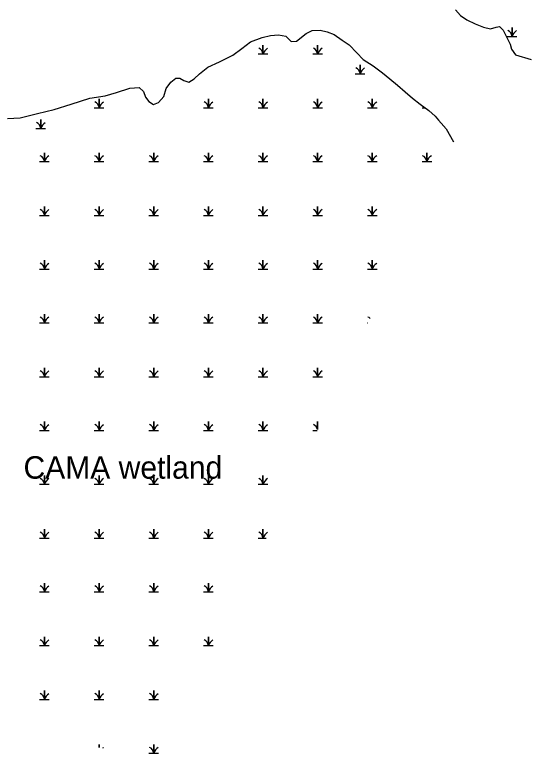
# Model space of a CAD drawing. Extents: x 2678633 to 2679425, y 623836 to 624637.
# Drawn here: x 2679137.9 to 2679367.7, y 623835.7 to 624164.5 of the extents above; entities that cross this region are included whole.
import ezdxf

# ---------------------------------------------------------------- set-up
doc = ezdxf.new("R2010")
doc.units = 0
for name, color, linetype in [('Exist Environmental Wetland Boundary Text', 7, 'Continuous'), ('Exist Hydro Jurisdictional Stream or Body of Water NEU Mitigable', 7, 'Continuous'), ('Exist Hydro Swamp or Marsh', 7, 'Continuous')]:
    doc.layers.add(name, color=color, linetype=linetype)

msp = doc.modelspace()

# ---------------------------------------------------------------- linework, layer by layer
at = {"layer": 'Exist Hydro Jurisdictional Stream or Body of Water NEU Mitigable'}
for points in [[(2679334.08, 624166.66), (2679336.33, 624164.17), (2679339.07, 624162.2), (2679342.8, 624160.42), (2679346.48, 624158.91), (2679349.63, 624158.24), (2679352.09, 624158.97), (2679353.62, 624159.26), (2679355.24, 624157.61), (2679358.4, 624151.43), (2679358.97, 624149.18), (2679360.71, 624146.65), (2679367.73, 624144.62)], [(2679134.61, 624118.28), (2679140.32, 624118.54), (2679148.07, 624120.5), (2679155.36, 624122.34), (2679162.99, 624124.69), (2679171.25, 624127.4), (2679178.18, 624128.34), (2679183.22, 624129.83), (2679189.12, 624131.8), (2679193.26, 624132.05), (2679195.22, 624130.3), (2679196.06, 624127.78), (2679197.62, 624125.82), (2679199.59, 624124.48), (2679201.9, 624125.43), (2679204.16, 624128.12), (2679205.25, 624131.69), (2679207.39, 624134.48), (2679209.56, 624136.27), (2679211.29, 624136.22), (2679213.18, 624135.22), (2679215.4, 624134.49), (2679217.68, 624135.97), (2679220.11, 624138.13), (2679223.75, 624141.11), (2679229.04, 624143.47), (2679234.87, 624146.52), (2679238.99, 624149.51), (2679242.78, 624152.42), (2679248.03, 624154.34), (2679251.69, 624155.25), (2679255.22, 624155.61), (2679258.48, 624154.9), (2679260.89, 624152.59), (2679263.21, 624152.67), (2679267.57, 624156.14), (2679270.19, 624157.44), (2679273.82, 624157.6), (2679276.99, 624156.87), (2679280.02, 624155.71), (2679283.63, 624153.2), (2679286.68, 624151.13), (2679290.11, 624147.47), (2679292.95, 624144.59), (2679297.35, 624141.67), (2679301.58, 624138.59), (2679304.86, 624135.98), (2679308.27, 624133.13), (2679311.62, 624130.12), (2679314.85, 624127.33), (2679318.38, 624124.68), (2679322.22, 624121.85), (2679324.99, 624119.26), (2679326.47, 624117.59), (2679327.71, 624116.19), (2679329.95, 624113.66), (2679333.14, 624107.89)]]:
    msp.add_lwpolyline(points, dxfattribs=at)
at = {"layer": 'Exist Hydro Swamp or Marsh'}
for p, q in [((2679291.57, 624140), (2679291.57, 624140)), ((2679149.43, 624115.64), (2679149.43, 624115.64))]:
    msp.add_line(p, q, dxfattribs=at)
for points in [[(2679357.05, 624154.87), (2679359.2, 624154.87), (2679359.2, 624158.81), (2679359.2, 624154.87), (2679361.35, 624154.87)], [(2679246.2, 624147.01), (2679248.36, 624147.01), (2679248.36, 624150.96), (2679248.36, 624147.01), (2679250.51, 624147.01)], [(2679270.52, 624147.01), (2679272.67, 624147.01), (2679272.67, 624150.96), (2679272.67, 624147.01), (2679274.82, 624147.01)], [(2679289.42, 624138.22), (2679291.57, 624138.22), (2679291.57, 624142.16), (2679291.57, 624138.22), (2679293.72, 624138.22)], [(2679173.27, 624123.06), (2679175.42, 624123.06), (2679175.42, 624127.01), (2679175.42, 624123.06), (2679177.57, 624123.06)], [(2679221.89, 624123.06), (2679224.04, 624123.06), (2679224.04, 624127.01), (2679224.04, 624123.06), (2679226.19, 624123.06)], [(2679246.2, 624123.06), (2679248.36, 624123.06), (2679248.36, 624127.01), (2679248.36, 624123.06), (2679250.51, 624123.06)], [(2679270.52, 624123.06), (2679272.67, 624123.06), (2679272.67, 624127.01), (2679272.67, 624123.06), (2679274.82, 624123.06)], [(2679294.83, 624123.06), (2679296.98, 624123.06), (2679296.98, 624127.01), (2679296.98, 624123.06), (2679299.13, 624123.06)], [(2679319.14, 624123.06), (2679320.58, 624123.06)], [(2679147.28, 624113.86), (2679149.43, 624113.86), (2679149.43, 624117.8), (2679149.43, 624113.86), (2679151.58, 624113.86)], [(2679148.95, 624099.11), (2679151.11, 624099.11), (2679151.11, 624103.06), (2679151.11, 624099.11), (2679153.26, 624099.11)], [(2679173.27, 624099.11), (2679175.42, 624099.11), (2679175.42, 624103.06), (2679175.42, 624099.11), (2679177.57, 624099.11)], [(2679197.58, 624099.11), (2679199.73, 624099.11), (2679199.73, 624103.06), (2679199.73, 624099.11), (2679201.88, 624099.11)], [(2679221.89, 624099.11), (2679224.04, 624099.11), (2679224.04, 624103.06), (2679224.04, 624099.11), (2679226.19, 624099.11)], [(2679246.2, 624099.11), (2679248.36, 624099.11), (2679248.36, 624103.06), (2679248.36, 624099.11), (2679250.51, 624099.11)], [(2679270.52, 624099.11), (2679272.67, 624099.11), (2679272.67, 624103.06), (2679272.67, 624099.11), (2679274.82, 624099.11)], [(2679294.83, 624099.11), (2679296.98, 624099.11), (2679296.98, 624103.06), (2679296.98, 624099.11), (2679299.13, 624099.11)], [(2679319.14, 624099.11), (2679321.29, 624099.11), (2679321.29, 624103.06), (2679321.29, 624099.11), (2679323.44, 624099.11)], [(2679148.95, 624075.16), (2679151.11, 624075.16), (2679151.11, 624079.11), (2679151.11, 624075.16), (2679153.26, 624075.16)], [(2679173.27, 624075.16), (2679175.42, 624075.16), (2679175.42, 624079.11), (2679175.42, 624075.16), (2679177.57, 624075.16)], [(2679197.58, 624075.16), (2679199.73, 624075.16), (2679199.73, 624079.11), (2679199.73, 624075.16), (2679201.88, 624075.16)], [(2679221.89, 624075.16), (2679224.04, 624075.16), (2679224.04, 624079.11), (2679224.04, 624075.16), (2679226.19, 624075.16)], [(2679246.2, 624075.16), (2679248.36, 624075.16), (2679248.36, 624079.11), (2679248.36, 624075.16), (2679250.51, 624075.16)], [(2679270.52, 624075.16), (2679272.67, 624075.16), (2679272.67, 624079.11), (2679272.67, 624075.16), (2679274.82, 624075.16)], [(2679294.83, 624075.16), (2679296.98, 624075.16), (2679296.98, 624079.11), (2679296.98, 624075.16), (2679299.13, 624075.16)], [(2679148.95, 624051.21), (2679151.11, 624051.21), (2679151.11, 624055.16), (2679151.11, 624051.21), (2679153.26, 624051.21)], [(2679173.27, 624051.21), (2679175.42, 624051.21), (2679175.42, 624055.16), (2679175.42, 624051.21), (2679177.57, 624051.21)], [(2679197.58, 624051.21), (2679199.73, 624051.21), (2679199.73, 624055.16), (2679199.73, 624051.21), (2679201.88, 624051.21)], [(2679221.89, 624051.21), (2679224.04, 624051.21), (2679224.04, 624055.16), (2679224.04, 624051.21), (2679226.19, 624051.21)], [(2679246.2, 624051.21), (2679248.36, 624051.21), (2679248.36, 624055.16), (2679248.36, 624051.21), (2679250.51, 624051.21)], [(2679270.52, 624051.21), (2679272.67, 624051.21), (2679272.67, 624055.16), (2679272.67, 624051.21), (2679274.82, 624051.21)], [(2679294.83, 624051.21), (2679296.98, 624051.21), (2679296.98, 624055.16), (2679296.98, 624051.21), (2679299.13, 624051.21)], [(2679148.95, 624027.26), (2679151.11, 624027.26), (2679151.11, 624031.21), (2679151.11, 624027.26), (2679153.26, 624027.26)], [(2679173.27, 624027.26), (2679175.42, 624027.26), (2679175.42, 624031.21), (2679175.42, 624027.26), (2679177.57, 624027.26)], [(2679197.58, 624027.26), (2679199.73, 624027.26), (2679199.73, 624031.21), (2679199.73, 624027.26), (2679201.88, 624027.26)], [(2679221.89, 624027.26), (2679224.04, 624027.26), (2679224.04, 624031.21), (2679224.04, 624027.26), (2679226.19, 624027.26)], [(2679246.2, 624027.26), (2679248.36, 624027.26), (2679248.36, 624031.21), (2679248.36, 624027.26), (2679250.51, 624027.26)], [(2679270.52, 624027.26), (2679272.67, 624027.26), (2679272.67, 624031.21), (2679272.67, 624027.26), (2679274.82, 624027.26)], [(2679294.83, 624027.26), (2679295.06, 624027.26)], [(2679148.95, 624003.31), (2679151.11, 624003.31), (2679151.11, 624007.26), (2679151.11, 624003.31), (2679153.26, 624003.31)], [(2679173.27, 624003.31), (2679175.42, 624003.31), (2679175.42, 624007.26), (2679175.42, 624003.31), (2679177.57, 624003.31)], [(2679197.58, 624003.31), (2679199.73, 624003.31), (2679199.73, 624007.26), (2679199.73, 624003.31), (2679201.88, 624003.31)], [(2679221.89, 624003.31), (2679224.04, 624003.31), (2679224.04, 624007.26), (2679224.04, 624003.31), (2679226.19, 624003.31)], [(2679246.2, 624003.31), (2679248.36, 624003.31), (2679248.36, 624007.26), (2679248.36, 624003.31), (2679250.51, 624003.31)], [(2679270.52, 624003.31), (2679272.67, 624003.31), (2679272.67, 624007.26), (2679272.67, 624003.31), (2679274.82, 624003.31)], [(2679148.95, 623979.36), (2679151.11, 623979.36), (2679151.11, 623983.31), (2679151.11, 623979.36), (2679153.26, 623979.36)], [(2679173.27, 623979.36), (2679175.42, 623979.36), (2679175.42, 623983.31), (2679175.42, 623979.36), (2679177.57, 623979.36)], [(2679197.58, 623979.36), (2679199.73, 623979.36), (2679199.73, 623983.31), (2679199.73, 623979.36), (2679201.88, 623979.36)], [(2679221.89, 623979.36), (2679224.04, 623979.36), (2679224.04, 623983.31), (2679224.04, 623979.36), (2679226.19, 623979.36)], [(2679246.2, 623979.36), (2679248.36, 623979.36), (2679248.36, 623983.31), (2679248.36, 623979.36), (2679250.51, 623979.36)], [(2679272.67, 623979.85), (2679272.67, 623983.31), (2679272.67, 623979.85)], [(2679270.52, 623979.36), (2679272.44, 623979.36)], [(2679148.95, 623955.41), (2679151.11, 623955.41), (2679151.11, 623959.36), (2679151.11, 623955.41), (2679153.26, 623955.41)], [(2679173.27, 623955.41), (2679175.42, 623955.41), (2679175.42, 623959.36), (2679175.42, 623955.41), (2679177.57, 623955.41)], [(2679197.58, 623955.41), (2679199.73, 623955.41), (2679199.73, 623959.36), (2679199.73, 623955.41), (2679201.88, 623955.41)], [(2679221.89, 623955.41), (2679224.04, 623955.41), (2679224.04, 623959.36), (2679224.04, 623955.41), (2679226.19, 623955.41)], [(2679246.2, 623955.41), (2679248.36, 623955.41), (2679248.36, 623959.36), (2679248.36, 623955.41), (2679250.51, 623955.41)], [(2679148.95, 623931.46), (2679151.11, 623931.46), (2679151.11, 623935.41), (2679151.11, 623931.46), (2679153.26, 623931.46)], [(2679173.27, 623931.46), (2679175.42, 623931.46), (2679175.42, 623935.41), (2679175.42, 623931.46), (2679177.57, 623931.46)], [(2679197.58, 623931.46), (2679199.73, 623931.46), (2679199.73, 623935.41), (2679199.73, 623931.46), (2679201.88, 623931.46)], [(2679221.89, 623931.46), (2679224.04, 623931.46), (2679224.04, 623935.41), (2679224.04, 623931.46), (2679226.19, 623931.46)], [(2679246.2, 623931.46), (2679248.36, 623931.46), (2679248.36, 623935.41), (2679248.36, 623931.46), (2679249.81, 623931.46)], [(2679148.95, 623907.51), (2679151.11, 623907.51), (2679151.11, 623911.46), (2679151.11, 623907.51), (2679153.26, 623907.51)], [(2679173.27, 623907.51), (2679175.42, 623907.51), (2679175.42, 623911.46), (2679175.42, 623907.51), (2679177.57, 623907.51)], [(2679197.58, 623907.51), (2679199.73, 623907.51), (2679199.73, 623911.46), (2679199.73, 623907.51), (2679201.88, 623907.51)], [(2679221.89, 623907.51), (2679224.04, 623907.51), (2679224.04, 623911.46), (2679224.04, 623907.51), (2679226.19, 623907.51)], [(2679148.95, 623883.56), (2679151.11, 623883.56), (2679151.11, 623887.51), (2679151.11, 623883.56), (2679153.26, 623883.56)], [(2679173.27, 623883.56), (2679175.42, 623883.56), (2679175.42, 623887.51), (2679175.42, 623883.56), (2679177.57, 623883.56)], [(2679197.58, 623883.56), (2679199.73, 623883.56), (2679199.73, 623887.51), (2679199.73, 623883.56), (2679201.88, 623883.56)], [(2679221.89, 623883.56), (2679224.04, 623883.56), (2679224.04, 623887.51), (2679224.04, 623883.56), (2679226.19, 623883.56)], [(2679148.95, 623859.61), (2679151.11, 623859.61), (2679151.11, 623863.56), (2679151.11, 623859.61), (2679153.26, 623859.61)], [(2679173.27, 623859.61), (2679175.42, 623859.61), (2679175.42, 623863.56), (2679175.42, 623859.61), (2679177.57, 623859.61)], [(2679197.58, 623859.61), (2679199.73, 623859.61), (2679199.73, 623863.56), (2679199.73, 623859.61), (2679201.88, 623859.61)], [(2679175.42, 623838.21), (2679175.42, 623839.61), (2679175.42, 623838.21)], [(2679197.58, 623835.66), (2679199.73, 623835.66), (2679199.73, 623839.61), (2679199.73, 623835.66), (2679201.88, 623835.66)]]:
    msp.add_lwpolyline(points, dxfattribs=at)
for centre, radius, start, end in [((2679356.14, 624154.65), 3.07, 4.1403, 67.535), ((2679363.76, 624153.35), 4.81, 122.1274, 161.6222), ((2679245.29, 624146.79), 3.07, 4.1403, 67.535), ((2679252.92, 624145.5), 4.81, 122.1274, 161.6222), ((2679269.6, 624146.79), 3.07, 4.1403, 67.535), ((2679277.23, 624145.5), 4.81, 122.1274, 161.6222), ((2679288.5, 624138), 3.07, 4.1403, 67.535), ((2679296.13, 624136.7), 4.81, 122.1274, 161.6222), ((2679172.35, 624122.84), 3.07, 4.1403, 67.535), ((2679179.98, 624121.55), 4.81, 122.1274, 161.6222), ((2679220.98, 624122.84), 3.07, 4.1403, 67.535), ((2679228.6, 624121.55), 4.81, 122.1274, 161.6222), ((2679245.29, 624122.84), 3.07, 4.1403, 67.535), ((2679252.92, 624121.55), 4.81, 122.1274, 161.6222), ((2679269.6, 624122.84), 3.07, 4.1403, 67.535), ((2679277.23, 624121.55), 4.81, 122.1274, 161.6222), ((2679293.91, 624122.84), 3.07, 4.1403, 67.535), ((2679301.54, 624121.55), 4.81, 122.1274, 161.6222), ((2679146.36, 624113.64), 3.07, 4.1403, 67.535), ((2679153.99, 624112.34), 4.81, 122.1274, 161.6222), ((2679148.04, 624098.89), 3.07, 4.1403, 67.535), ((2679155.67, 624097.6), 4.81, 122.1274, 161.6222), ((2679172.35, 624098.89), 3.07, 4.1403, 67.535), ((2679179.98, 624097.6), 4.81, 122.1274, 161.6222), ((2679196.66, 624098.89), 3.07, 4.1403, 67.535), ((2679204.29, 624097.6), 4.81, 122.1274, 161.6222), ((2679220.98, 624098.89), 3.07, 4.1403, 67.535), ((2679228.6, 624097.6), 4.81, 122.1274, 161.6222), ((2679245.29, 624098.89), 3.07, 4.1403, 67.535), ((2679252.92, 624097.6), 4.81, 122.1274, 161.6222), ((2679269.6, 624098.89), 3.07, 4.1403, 67.535), ((2679277.23, 624097.6), 4.81, 122.1274, 161.6222), ((2679293.91, 624098.89), 3.07, 4.1403, 67.535), ((2679301.54, 624097.6), 4.81, 122.1274, 161.6222), ((2679318.23, 624098.89), 3.07, 4.1403, 67.535), ((2679325.85, 624097.6), 4.81, 122.1274, 161.6222), ((2679148.04, 624074.94), 3.07, 4.1403, 67.535), ((2679155.67, 624073.65), 4.81, 122.1274, 161.6222), ((2679172.35, 624074.94), 3.07, 4.1403, 67.535), ((2679179.98, 624073.65), 4.81, 122.1274, 161.6222), ((2679196.66, 624074.94), 3.07, 4.1403, 67.535), ((2679204.29, 624073.65), 4.81, 122.1274, 161.6222), ((2679220.98, 624074.94), 3.07, 4.1403, 67.535), ((2679228.6, 624073.65), 4.81, 122.1274, 161.6222), ((2679245.29, 624074.94), 3.07, 4.1403, 67.535), ((2679252.92, 624073.65), 4.81, 122.1274, 161.6222), ((2679269.6, 624074.94), 3.07, 4.1403, 67.535), ((2679277.23, 624073.65), 4.81, 122.1274, 161.6222), ((2679293.91, 624074.94), 3.07, 4.1403, 67.535), ((2679301.54, 624073.65), 4.81, 122.1274, 161.6222), ((2679148.04, 624050.99), 3.07, 4.1403, 67.535), ((2679155.67, 624049.7), 4.81, 122.1274, 161.6222), ((2679172.35, 624050.99), 3.07, 4.1403, 67.535), ((2679179.98, 624049.7), 4.81, 122.1274, 161.6222), ((2679196.66, 624050.99), 3.07, 4.1403, 67.535), ((2679204.29, 624049.7), 4.81, 122.1274, 161.6222), ((2679220.98, 624050.99), 3.07, 4.1403, 67.535), ((2679228.6, 624049.7), 4.81, 122.1274, 161.6222), ((2679245.29, 624050.99), 3.07, 4.1403, 67.535), ((2679252.92, 624049.7), 4.81, 122.1274, 161.6222), ((2679269.6, 624050.99), 3.07, 4.1403, 67.535), ((2679277.23, 624049.7), 4.81, 122.1274, 161.6222), ((2679293.91, 624050.99), 3.07, 4.1403, 67.535), ((2679301.54, 624049.7), 4.81, 122.1274, 161.6222), ((2679148.04, 624027.04), 3.07, 4.1403, 67.535), ((2679155.67, 624025.75), 4.81, 122.1274, 161.6222), ((2679172.35, 624027.04), 3.07, 4.1403, 67.535), ((2679179.98, 624025.75), 4.81, 122.1274, 161.6222), ((2679196.66, 624027.04), 3.07, 4.1403, 67.535), ((2679204.29, 624025.75), 4.81, 122.1274, 161.6222), ((2679220.98, 624027.04), 3.07, 4.1403, 67.535), ((2679228.6, 624025.75), 4.81, 122.1274, 161.6222), ((2679245.29, 624027.04), 3.07, 4.1403, 67.535), ((2679252.92, 624025.75), 4.81, 122.1274, 161.6222), ((2679269.6, 624027.04), 3.07, 4.1403, 67.535), ((2679277.23, 624025.75), 4.81, 122.1274, 161.6222), ((2679293.91, 624027.04), 3.07, 46.8859, 67.535), ((2679148.04, 624003.09), 3.07, 4.1403, 67.535), ((2679155.67, 624001.8), 4.81, 122.1274, 161.6222), ((2679172.35, 624003.09), 3.07, 4.1403, 67.535), ((2679179.98, 624001.8), 4.81, 122.1274, 161.6222), ((2679196.66, 624003.09), 3.07, 4.1403, 67.535), ((2679204.29, 624001.8), 4.81, 122.1274, 161.6222), ((2679220.98, 624003.09), 3.07, 4.1403, 67.535), ((2679228.6, 624001.8), 4.81, 122.1274, 161.6222), ((2679245.29, 624003.09), 3.07, 4.1403, 67.535), ((2679252.92, 624001.8), 4.81, 122.1274, 161.6222), ((2679269.6, 624003.09), 3.07, 4.1403, 67.535), ((2679277.23, 624001.8), 4.81, 122.1274, 161.6222), ((2679148.04, 623979.14), 3.07, 4.1403, 67.535), ((2679155.67, 623977.85), 4.81, 122.1274, 161.6222), ((2679172.35, 623979.14), 3.07, 4.1403, 67.535), ((2679179.98, 623977.85), 4.81, 122.1274, 161.6222), ((2679196.66, 623979.14), 3.07, 4.1403, 67.535), ((2679204.29, 623977.85), 4.81, 122.1274, 161.6222), ((2679220.98, 623979.14), 3.07, 4.1403, 67.535), ((2679228.6, 623977.85), 4.81, 122.1274, 161.6222), ((2679245.29, 623979.14), 3.07, 4.1403, 67.535), ((2679252.92, 623977.85), 4.81, 122.1274, 161.6222), ((2679269.6, 623979.14), 3.07, 11.2994, 67.535), ((2679148.04, 623955.19), 3.07, 4.1403, 67.535), ((2679155.67, 623953.9), 4.81, 122.1274, 161.6222), ((2679172.35, 623955.19), 3.07, 4.1403, 67.535), ((2679179.98, 623953.9), 4.81, 122.1274, 161.6222), ((2679196.66, 623955.19), 3.07, 4.1403, 67.535), ((2679204.29, 623953.9), 4.81, 122.1274, 161.6222), ((2679220.98, 623955.19), 3.07, 4.1403, 67.535), ((2679228.6, 623953.9), 4.81, 122.1274, 161.6222), ((2679245.29, 623955.19), 3.07, 4.1403, 67.535), ((2679252.92, 623953.9), 4.81, 122.1274, 161.6222), ((2679148.04, 623931.24), 3.07, 4.1403, 67.535), ((2679155.67, 623929.95), 4.81, 122.1274, 161.6222), ((2679172.35, 623931.24), 3.07, 4.1403, 67.535), ((2679179.98, 623929.95), 4.81, 122.1274, 161.6222), ((2679196.66, 623931.24), 3.07, 4.1403, 67.535), ((2679204.29, 623929.95), 4.81, 122.1274, 161.6222), ((2679220.98, 623931.24), 3.07, 4.1403, 67.535), ((2679228.6, 623929.95), 4.81, 122.1274, 161.6222), ((2679245.29, 623931.24), 3.07, 4.1403, 67.535), ((2679252.92, 623929.95), 4.81, 122.1274, 161.6222), ((2679148.04, 623907.29), 3.07, 4.1403, 67.535), ((2679155.67, 623906), 4.81, 122.1274, 161.6222), ((2679172.35, 623907.29), 3.07, 4.1403, 67.535), ((2679179.98, 623906), 4.81, 122.1274, 161.6222), ((2679196.66, 623907.29), 3.07, 4.1403, 67.535), ((2679204.29, 623906), 4.81, 122.1274, 161.6222), ((2679220.98, 623907.29), 3.07, 4.1403, 67.535), ((2679228.6, 623906), 4.81, 122.1274, 161.6222), ((2679148.04, 623883.34), 3.07, 4.1403, 67.535), ((2679155.67, 623882.05), 4.81, 122.1274, 161.6222), ((2679172.35, 623883.34), 3.07, 4.1403, 67.535), ((2679179.98, 623882.05), 4.81, 122.1274, 161.6222), ((2679196.66, 623883.34), 3.07, 4.1403, 67.535), ((2679204.29, 623882.05), 4.81, 122.1274, 161.6222), ((2679220.98, 623883.34), 3.07, 4.1403, 67.535), ((2679228.6, 623882.05), 4.81, 122.1274, 161.6222), ((2679148.04, 623859.39), 3.07, 4.1403, 67.535), ((2679155.67, 623858.1), 4.81, 122.1274, 161.6222), ((2679172.35, 623859.39), 3.07, 4.1403, 67.535), ((2679179.98, 623858.1), 4.81, 122.1274, 161.6222), ((2679196.66, 623859.39), 3.07, 4.1403, 67.535), ((2679204.29, 623858.1), 4.81, 122.1274, 161.6222), ((2679179.98, 623834.15), 4.81, 122.1274, 129.1388), ((2679196.66, 623835.44), 3.07, 4.1403, 67.535), ((2679204.29, 623834.15), 4.81, 122.1274, 161.6222)]:
    msp.add_arc(centre, radius, start, end, dxfattribs=at)

# ---------------------------------------------------------------- texts
at = {"layer": 'Exist Environmental Wetland Boundary Text'}
msp.add_text('CAMA wetland', height=10, dxfattribs=at).set_placement((2679141.78, 623957.91))

doc.saveas('drawing.dxf')
